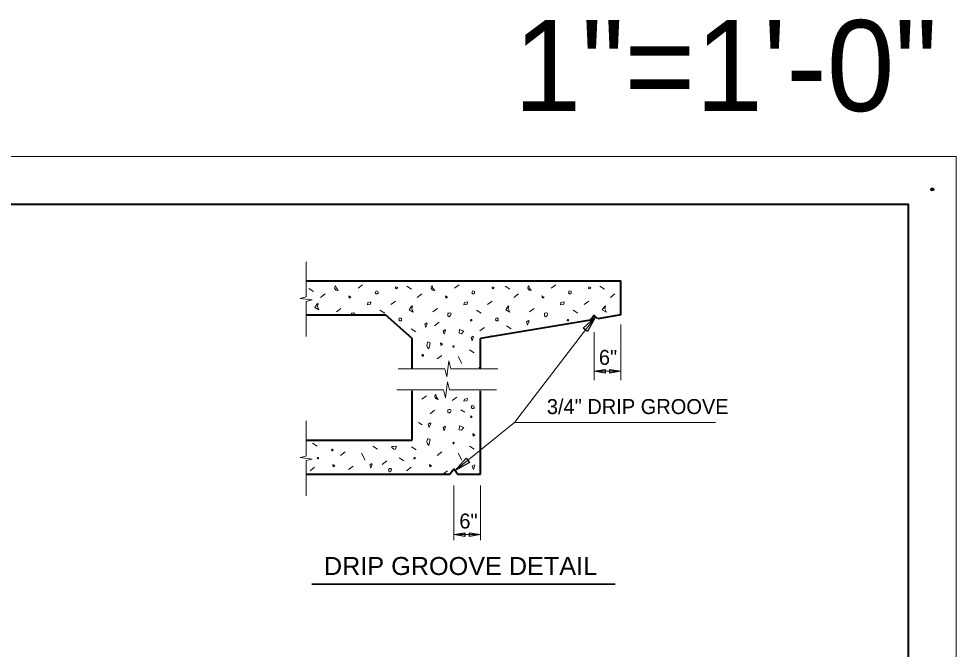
# Model space of a CAD drawing. Extents: x 0 to 34, y 0 to 23.4.
# Drawn here: x 24.21 to 34, y 16.86 to 23.44 of the extents above; entities that cross this region are included whole.
import ezdxf
from ezdxf.enums import TextEntityAlignment as Align

# ---------------------------------------------------------------- set-up
doc = ezdxf.new("R2010")
doc.units = 0
doc.header["$LTSCALE"] = 0.062
doc.header["$PDMODE"] = 32
doc.header["$PDSIZE"] = 0.031
for name, color, linetype, lineweight in [('1', 7, 'Continuous', 40), ('4', 7, 'Continuous', 13), ('7', 7, 'Continuous', 13)]:
    doc.layers.add(name, color=color, linetype=linetype, lineweight=lineweight)
doc.layers.add('49', color=7, linetype='Continuous')

msp = doc.modelspace()

# ---------------------------------------------------------------- linework, layer by layer
at = {"layer": '1', "lineweight": 13}
for p, q in [((27.21313, 20.53495), (27.21313, 20.90214)), ((27.21313, 20.12089), (27.21313, 20.48807)), ((28.66224, 19.78464), (28.17266, 19.78464)), ((29.21432, 19.78464), (28.72474, 19.78464)), ((28.64839, 19.56313), (28.1588, 19.56313)), ((29.20047, 19.56313), (28.71089, 19.56313)), ((27.21313, 18.87349), (27.21313, 19.24068)), ((27.21313, 18.45943), (27.21313, 18.82661))]:
    msp.add_line(p, q, dxfattribs=at)
at = {"layer": '1'}
for p, q in [((27.21167, 20.70203), (30.49708, 20.70203)), ((30.49708, 20.34578), (30.49708, 20.70203)), ((27.21167, 20.34578), (28.04292, 20.34578)), ((28.32, 20.09859), (28.04292, 20.34578)), ((30.18042, 20.29234), (29.0325, 20.09859)), ((30.49708, 20.34578), (30.25958, 20.30573)), ((28.32, 19.79161), (28.32, 20.09859)), ((29.0325, 19.79161), (29.0325, 20.09859)), ((28.32, 19.03953), (28.32, 19.55411)), ((29.0325, 18.68328), (29.0325, 19.55411)), ((27.21167, 19.03953), (28.32, 19.03953)), ((28.71443, 18.68328), (28.75542, 18.74057)), ((28.79365, 18.68328), (28.75542, 18.74057)), ((27.21167, 18.68328), (28.71443, 18.68328)), ((28.79365, 18.68328), (29.0325, 18.68328))]:
    msp.add_line(p, q, dxfattribs=at)
at = {"layer": '1', "lineweight": 13}
for points in [[(34, 0), (34, 22), (0, 22)], [(27.21313, 20.53495), (27.15063, 20.51932), (27.27563, 20.5037), (27.21313, 20.48807)], [(28.66224, 19.78464), (28.68307, 19.7013), (28.70391, 19.86797), (28.72474, 19.78464)], [(28.64839, 19.56313), (28.66922, 19.47979), (28.69005, 19.64646), (28.71089, 19.56313)], [(27.21313, 18.87349), (27.15063, 18.85786), (27.27563, 18.84224), (27.21313, 18.82661)]]:
    msp.add_lwpolyline(points, dxfattribs=at)
at = {"layer": '1'}
msp.add_lwpolyline([(33.5, 0.5), (33.5, 21.5), (1.5, 21.5), (1.5, 0.5)], close=True, dxfattribs=at)
msp.add_lwpolyline([(30.25958, 20.30563), (30.22, 20.34052), (30.18042, 20.29245)], dxfattribs=at)
at = {"layer": '4'}
for p, q in [((29.38901, 19.22214), (30.2326, 20.32698)), ((30.22, 19.66693), (30.22, 20.16693)), ((30.49708, 19.66693), (30.49708, 20.24703)), ((30.22, 19.7576), (30.49708, 19.7576)), ((29.38901, 19.22214), (28.76901, 18.72125)), ((29.38901, 19.22214), (31.48839, 19.22214)), ((28.75542, 17.99375), (28.75542, 18.5649)), ((29.0325, 17.99375), (29.0325, 18.5649)), ((28.75542, 18.05385), (29.0325, 18.05385))]:
    msp.add_line(p, q, dxfattribs=at)
at = {"layer": '4', "lineweight": 35}
msp.add_line((27.27188, 17.53641), (30.44026, 17.53641), dxfattribs=at)
at = {"layer": '4', "lineweight": 25}
for points in [[(30.15146, 20.17375), (30.1062, 20.20839), (30.2326, 20.32698)], [(30.33401, 19.77661), (30.33401, 19.73859), (30.22, 19.7576)], [(30.38307, 19.73859), (30.38307, 19.77661), (30.49708, 19.7576)], [(28.88411, 18.85089), (28.91995, 18.80656), (28.76901, 18.72125)], [(28.86943, 18.07286), (28.86943, 18.03484), (28.75542, 18.05385)], [(28.91849, 18.03484), (28.91849, 18.07286), (29.0325, 18.05385)]]:
    msp.add_lwpolyline(points, close=True, dxfattribs=at)
at = {"layer": '49'}
msp.add_point((33.75, 21.65625), dxfattribs=at)
at = {"layer": '7'}
for p, q in [((27.80302, 20.66062), (27.7549, 20.62401)), ((28.81141, 20.66062), (28.76328, 20.62401)), ((29.81979, 20.66062), (29.77167, 20.62401)), ((27.24214, 20.62052), (27.29161, 20.58927)), ((27.41193, 20.56505), (27.3638, 20.52844)), ((28.26271, 20.6449), (28.31219, 20.61365)), ((28.42031, 20.56505), (28.37219, 20.52844)), ((29.28932, 20.6449), (29.3388, 20.61365)), ((29.4287, 20.56505), (29.38057, 20.52844)), ((30.27943, 20.6449), (30.32891, 20.61365)), ((30.43708, 20.56505), (30.38896, 20.52844)), ((28.14677, 20.49036), (28.09865, 20.45375)), ((29.15516, 20.49036), (29.10703, 20.45375)), ((30.16354, 20.49036), (30.11542, 20.45375)), ((27.57698, 20.41391), (27.52885, 20.37729)), ((27.68516, 20.36359), (27.68516, 20.34578)), ((27.98375, 20.39427), (28.03328, 20.36307)), ((28.58536, 20.41391), (28.53724, 20.37729)), ((28.99214, 20.39427), (29.04167, 20.36307)), ((29.59375, 20.41391), (29.54563, 20.37729)), ((30.00052, 20.39427), (30.05005, 20.36307)), ((28.60188, 20.26948), (28.55375, 20.23286)), ((28.30813, 20.20068), (28.35755, 20.16964)), ((29.07406, 20.21563), (29.02594, 20.17901)), ((29.30432, 20.23109), (29.35375, 20.20005)), ((29.14297, 20.1324), (29.16193, 20.12042)), ((28.91786, 19.9826), (28.96734, 19.95135)), ((28.6288, 19.92292), (28.58068, 19.8863)), ((28.80036, 19.91182), (28.83703, 19.83828)), ((29.0325, 19.80542), (29.01563, 19.79255)), ((28.46906, 19.50286), (28.42094, 19.46625)), ((28.78703, 19.48875), (28.73891, 19.45214)), ((28.5549, 19.35172), (28.50677, 19.3151)), ((28.82776, 19.35646), (28.86813, 19.33104)), ((28.38698, 19.2224), (28.42453, 19.1988)), ((27.27917, 19.00604), (27.32859, 18.97474)), ((27.62042, 18.91557), (27.57229, 18.87896)), ((27.79198, 18.90448), (27.82865, 18.83094)), ((27.90948, 18.97526), (27.95896, 18.94401)), ((28.31188, 18.96948), (28.3613, 18.93818)), ((28.6288, 18.91557), (28.58068, 18.87896)), ((28.80036, 18.90448), (28.83703, 18.83094)), ((28.91786, 18.97526), (28.96734, 18.94401)), ((28.05536, 18.82182), (28.00724, 18.78521)), ((28.18281, 18.85448), (28.23229, 18.82323)), ((27.30161, 18.75682), (27.25349, 18.72021)), ((27.70313, 18.76865), (27.655, 18.73203)), ((28.31, 18.75682), (28.26188, 18.72021)), ((28.68714, 18.7199), (28.63901, 18.68328))]:
    msp.add_line(p, q, dxfattribs=at)
for points in [[(27.51443, 20.64568), (27.51036, 20.62495), (27.52411, 20.60464), (27.54714, 20.6001), (27.52875, 20.62448), (27.52089, 20.64979)], [(27.94339, 20.59859), (27.93411, 20.57839), (27.94495, 20.56714), (27.95818, 20.56714), (27.96359, 20.57302), (27.96359, 20.5838), (27.96177, 20.58911), (27.95604, 20.59505)], [(28.14635, 20.64021), (28.14547, 20.62042), (28.1574, 20.61766), (28.16891, 20.63099)], [(28.52281, 20.64568), (28.51875, 20.62495), (28.5325, 20.60464), (28.55552, 20.6001), (28.53714, 20.62448), (28.52927, 20.64979)], [(28.95177, 20.59859), (28.9425, 20.57839), (28.95333, 20.56714), (28.96656, 20.56714), (28.97198, 20.57302), (28.97198, 20.5838), (28.97016, 20.58911), (28.96443, 20.59505)], [(29.15474, 20.64021), (29.15385, 20.62042), (29.16578, 20.61766), (29.17729, 20.63099)], [(29.5312, 20.64568), (29.52714, 20.62495), (29.54089, 20.60464), (29.56391, 20.6001), (29.54552, 20.62448), (29.53766, 20.64979)], [(29.96016, 20.59859), (29.95089, 20.57839), (29.96172, 20.56714), (29.97495, 20.56714), (29.98036, 20.57302), (29.98036, 20.5838), (29.97854, 20.58911), (29.97281, 20.59505)], [(30.16313, 20.64021), (30.16224, 20.62042), (30.17417, 20.61766), (30.18568, 20.63099)], [(27.32964, 20.4637), (27.30391, 20.42516), (27.34719, 20.39922), (27.33141, 20.43427), (27.33807, 20.46635)], [(27.65859, 20.54667), (27.66229, 20.52083), (27.68078, 20.53193)], [(27.85641, 20.475), (27.85271, 20.45297), (27.87854, 20.45667), (27.88583, 20.46026), (27.88953, 20.4824)], [(28.66698, 20.54667), (28.67068, 20.52083), (28.68917, 20.53193)], [(28.86479, 20.475), (28.86109, 20.45297), (28.88693, 20.45667), (28.89422, 20.46026), (28.89792, 20.4824)], [(29.67536, 20.54667), (29.67906, 20.52083), (29.69755, 20.53193)], [(29.87318, 20.475), (29.86948, 20.45297), (29.89531, 20.45667), (29.9026, 20.46026), (29.9063, 20.4824)], [(28.3137, 20.43932), (28.28797, 20.40078), (28.33125, 20.37484), (28.31547, 20.4099), (28.32214, 20.44198)], [(28.69354, 20.36359), (28.69354, 20.33568), (28.7062, 20.32672), (28.71005, 20.33031), (28.72089, 20.34141), (28.72828, 20.3562), (28.72292, 20.36359), (28.71552, 20.36714), (28.71193, 20.36714), (28.70469, 20.3651)], [(29.32208, 20.43932), (29.29635, 20.40078), (29.33964, 20.37484), (29.32385, 20.4099), (29.33052, 20.44198)], [(29.70193, 20.36359), (29.70193, 20.33568), (29.71458, 20.32672), (29.71844, 20.33031), (29.72927, 20.34141), (29.73667, 20.3562), (29.7313, 20.36359), (29.72391, 20.36714), (29.72031, 20.36714), (29.71307, 20.3651)], [(30.33047, 20.43932), (30.30474, 20.40078), (30.34802, 20.37484), (30.33224, 20.4099), (30.33891, 20.44198)], [(28.18943, 20.31484), (28.18016, 20.29464), (28.19099, 20.28339), (28.20422, 20.28339), (28.20964, 20.28927), (28.20964, 20.30005), (28.20781, 20.30536), (28.20208, 20.3113)], [(28.45063, 20.24844), (28.46198, 20.21521), (28.46198, 20.21875), (28.47677, 20.25578), (28.47302, 20.26313)], [(28.93333, 20.29922), (28.9287, 20.28911), (28.93411, 20.28349), (28.94073, 20.28349), (28.94344, 20.28641), (28.94344, 20.29182), (28.94255, 20.29448), (28.93969, 20.29745)], [(29.19781, 20.31484), (29.18854, 20.29464), (29.19938, 20.28339), (29.2126, 20.28339), (29.21802, 20.28927), (29.21802, 20.30005), (29.2162, 20.30536), (29.21047, 20.3113)], [(29.5138, 20.27281), (29.52516, 20.23958), (29.52516, 20.24313), (29.53995, 20.28016), (29.5362, 20.2875)], [(29.94172, 20.29922), (29.93708, 20.28911), (29.9425, 20.28349), (29.94911, 20.28349), (29.95182, 20.28641), (29.95182, 20.29182), (29.95094, 20.29448), (29.94807, 20.29745)], [(28.64281, 20.17771), (28.65422, 20.14453), (28.65422, 20.14807), (28.66891, 20.1851), (28.66516, 20.19245)], [(28.81411, 20.19531), (28.81234, 20.15573), (28.83625, 20.15016), (28.85927, 20.17688)], [(28.48297, 20.06406), (28.47177, 20.03094), (28.47745, 20.01438), (28.49401, 19.99224), (28.50135, 20.02172), (28.50688, 20.0549)], [(28.9351, 20.10995), (28.94651, 20.07672), (28.94651, 20.08031), (28.9612, 20.11729), (28.95745, 20.12464)], [(28.61599, 20.05443), (28.61969, 20.02859), (28.63818, 20.03969)], [(28.74339, 20.01682), (28.7463, 20.0076), (28.74896, 20.0076), (28.75271, 20.00854), (28.75542, 20.0112), (28.75807, 20.01682), (28.75734, 20.02234), (28.75271, 20.02328), (28.75073, 20.02521), (28.74708, 20.02521)], [(28.42667, 19.93323), (28.42203, 19.92307), (28.42745, 19.91745), (28.43406, 19.91745), (28.43677, 19.92042), (28.43677, 19.92583), (28.43589, 19.92849), (28.43302, 19.93146)], [(28.55932, 19.51036), (28.55526, 19.48964), (28.56901, 19.46932), (28.59203, 19.46479), (28.57365, 19.48917), (28.56578, 19.51448)], [(28.86479, 19.46766), (28.86109, 19.44562), (28.88693, 19.44932), (28.89422, 19.45292), (28.89792, 19.47505)], [(28.94568, 19.4024), (28.93641, 19.38219), (28.94724, 19.37094), (28.96047, 19.37094), (28.96589, 19.37682), (28.96589, 19.3876), (28.96406, 19.39292), (28.95833, 19.39885)], [(28.69354, 19.35625), (28.69354, 19.32833), (28.7062, 19.31938), (28.71005, 19.32297), (28.72089, 19.33406), (28.72828, 19.34885), (28.72292, 19.35625), (28.71552, 19.35979), (28.71193, 19.35979), (28.70469, 19.35776)], [(28.93333, 19.29188), (28.9287, 19.28177), (28.93411, 19.27615), (28.94073, 19.27615), (28.94344, 19.27906), (28.94344, 19.28448), (28.94255, 19.28714), (28.93969, 19.2901)], [(28.48719, 19.20453), (28.49854, 19.1713), (28.49854, 19.17484), (28.51333, 19.21188), (28.50958, 19.21922)], [(28.64281, 19.17036), (28.65422, 19.13719), (28.65422, 19.14073), (28.66891, 19.17776), (28.66516, 19.1851)], [(28.81411, 19.18797), (28.81234, 19.14839), (28.83625, 19.14281), (28.85927, 19.16953)], [(28.95313, 19.10677), (28.95682, 19.08094), (28.97531, 19.09203)], [(28.48297, 19.05672), (28.47177, 19.02359), (28.47745, 19.00703), (28.49401, 18.9849), (28.50135, 19.01438), (28.50688, 19.04755)], [(28.74339, 19.00948), (28.7463, 19.00026), (28.74896, 19.00026), (28.75271, 19.0012), (28.75542, 19.00385), (28.75807, 19.00948), (28.75734, 19.015), (28.75271, 19.01594), (28.75073, 19.01786), (28.74708, 19.01786)], [(27.47927, 18.93641), (27.48219, 18.92719), (27.48484, 18.92719), (27.48859, 18.92813), (27.4913, 18.93078), (27.49396, 18.93641), (27.49323, 18.94193), (27.48859, 18.94286), (27.48661, 18.94479), (27.48297, 18.94479)], [(28.12833, 18.97385), (28.10625, 18.97198), (28.10625, 18.96094), (28.13021, 18.94443), (28.14318, 18.94255), (28.15609, 18.9775)], [(27.33307, 18.85885), (27.32844, 18.8487), (27.33385, 18.84307), (27.34047, 18.84307), (27.34318, 18.84604), (27.34318, 18.85146), (27.34229, 18.85411), (27.33943, 18.85708)], [(27.87802, 18.77969), (27.88943, 18.74646), (27.88943, 18.75005), (27.90411, 18.78703), (27.90036, 18.79438)], [(28.34146, 18.85885), (28.33682, 18.8487), (28.34224, 18.84307), (28.34885, 18.84307), (28.35156, 18.84604), (28.35156, 18.85146), (28.35068, 18.85411), (28.34781, 18.85708)], [(27.49198, 18.7851), (27.49568, 18.75927), (27.51417, 18.77036)], [(28.07464, 18.72797), (28.08047, 18.70953), (28.08578, 18.70953), (28.09328, 18.71135), (28.0987, 18.71672), (28.10406, 18.72797), (28.10255, 18.73891), (28.09328, 18.74083), (28.08938, 18.74464), (28.08203, 18.74464)], [(28.50036, 18.7851), (28.50406, 18.75927), (28.52255, 18.77036)], [(28.94724, 18.7675), (28.95865, 18.73427), (28.95865, 18.73786), (28.97333, 18.77484), (28.96958, 18.78219)]]:
    msp.add_lwpolyline(points, close=True, dxfattribs=at)
msp.add_lwpolyline([(27.71469, 20.34578), (27.7199, 20.3562), (27.71453, 20.36359), (27.70714, 20.36714), (27.70354, 20.36714), (27.6963, 20.3651), (27.68516, 20.36359)], dxfattribs=at)

# ---------------------------------------------------------------- texts
at = {"layer": '4'}
msp.add_text('1"=1\'-0"', height=0.9494, dxfattribs=at).set_placement((33.8051, 22.47438), align=Align.RIGHT)
for p in [(30.36445, 19.82484), (28.90789, 18.11625)]:
    msp.add_text('6"', height=0.1563, dxfattribs=at).set_placement(p, align=Align.CENTER)
msp.add_text('3/4" DRIP GROOVE', height=0.1563, dxfattribs=at).set_placement((29.72604, 19.31156))
at = {"layer": '4', "width": 1.05}
msp.add_text('DRIP GROOVE DETAIL', height=0.1875, dxfattribs=at).set_placement((28.82487, 17.63161), align=Align.CENTER)

doc.saveas('drawing.dxf')
